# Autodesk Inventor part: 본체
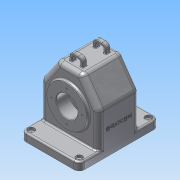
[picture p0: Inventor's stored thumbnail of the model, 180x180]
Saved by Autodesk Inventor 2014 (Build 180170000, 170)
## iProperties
Created: 2016-12
Part Number: 본체
Material: 알루미늄 6061
Document SubType Name: Modeling
Designer: net
Density: 2.71 g/cm^3
Appearance: 알루미늄 - 평지
Author: net
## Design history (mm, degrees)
sketch "스케치1"
  geometry: L1 (-55, 75)-(55, 75); L2 (55, 75)-(55, -75); L3 (55, -75)-(-55, -75); L4 (-55, -75)-(-55, 75); L5 (-55, 75)-(55, -75); L6 (55, 75)-(-55, -75); 1 further point
  constraints: 12 end point, 2 midpoint, 2 parallel, 1 horizontal, 1 perpendicular
  dimensions: "d0" = 110 distance between parallel lines of L4 L2; "d1" = 150 distance between parallel lines of L1 L3
extrude "돌출1" new body sketch "스케치1" distance "d2" = 15; taper "d3" = 0 deg
sketch "스케치2"
  geometry: L1 (-55, 80)-(-55, 15); L2 (-55, 15)-(55, 15); L3 (55, 15)-(55, 80); L4 (55, 80)-(23.491, 125); L5 (23.491, 125)-(-23.491, 125); L6 (-23.491, 125)-(-55, 80); L7 (55, 15)-(-55, 15) reference; L8 (-55, 0)-(-55, 15) reference; L9 (-55, 0)-(55, 0) reference; 3 further points
  constraints: 12 end point, 2 collinear, 2 midpoint, 2 parallel, 2 vertical alignment, 1 perpendicular, 1 vertical
  dimensions: "d4" = 35 deg angle of L1 L6; "d5" = 35 deg angle of L3 L4; "d6" = 125 distance between parallel lines of L9 L5; "d7" = 80 distance from line of L9 L3.end
extrude "돌출2" join sketch "스케치2" stored distance "d8" = 77; taper "d9" = 0 deg
sketch "스케치3"
  geometry: C1 r 37.5 at (0, 65); 1 further point
  constraints: 1 centre point, 1 vertical alignment
  dimensions: "d10" = 75 diameter of C1; "d11" = 65 distance of point (0, 0) C1.centre
extrude "돌출3" join sketch "스케치3" distance "d12" = 5; taper "d13" = 0 deg
sketch "스케치4"
  geometry: C1 r 37.5 at (0, 65) reference; C2 r 31 at (0, 65); 1 further point
  constraints: 1 centre point, 1 coincident
  dimensions: "d14" = 62 diameter of C2
extrude "돌출4" join sketch "스케치4" distance "d15" = 10; taper "d16" = 0 deg
sketch "스케치5"
  geometry: L1 (-55, 15)-(-55, 80) reference; L2 (-55, 80)-(-23.491, 125) reference; L3 (-23.491, 125)-(23.491, 125) reference; L4 (23.491, 125)-(55, 80) reference; L5 (55, 80)-(55, 15) reference; L6 (50, 0)-(50, 78.424); L7 (50, 78.424)-(20.888, 120); L8 (20.888, 120)-(-20.888, 120); L9 (-20.888, 120)-(-50, 78.424); L10 (-50, 78.424)-(-50, 0); L11 (-55, 0)-(55, 0) reference; L12 (-50, 0)-(50, 0); 1 further point
  constraints: 12 end point, 2 equal length, 2 point on line, 1 collinear, 2 other
  dimensions: "d17" = 5 distance between parallel lines of L5 L6; "d18" = 5 distance between parallel lines of L4 L7
extrude "돌출5" cut sketch "스케치5" stored distance "d19" = 67; taper "d20" = 0 deg
node "작업 평면1"
sketch "스케치13"
  geometry: C1 r 31 at (0, 0) reference; C2 r 27 at (0, 0); 1 further point
  constraints: 1 centre point, 1 coincident
  dimensions: "d132" = 54 diameter of C2
extrude "돌출10" join sketch "스케치13" stored distance "d133" = 15; taper "d134" = 45 deg
hole "구멍1" diameter "d23" = 40; stored, may be unused: countersink angle "d27" = 90 deg, drill point angle "d29" = 118 deg; dims "d21" = 10, "d22" = 10, "d24" = 6, "d25" = 4, "d26" = 2, "d28" = 8
sketch "스케치6"
  geometry: C1 r 20 at (0, 0) reference; 2 further points
  constraints: 1 vertical alignment
  dimensions: "d30" = 29 distance of C1.centre point (0, 29)
hole "구멍2" sketch "스케치6" at (0, 29) diameter "d31" = 2.459; stored, may be unused: countersink angle "d35" = 90 deg, drill point angle "d37" = 118 deg; dims "d32" = 6, "d33" = 4, "d34" = 2, "d36" = 8
sketch "스케치7"
  geometry: C1 r 20 at (0, 0) reference; 2 further points
  constraints: 1 vertical alignment
  dimensions: "d41" = 26 distance of C1.centre point (0, 26)
hole "구멍3" sketch "스케치7" at (0, 26) diameter "d42" = 2.459; stored, may be unused: countersink angle "d46" = 90 deg, drill point angle "d48" = 118 deg; dims "d43" = 6, "d44" = 4, "d45" = 2, "d47" = 8
fillet "모깎기1" dims "d52" = 10
sketch "스케치8"
  geometry: L1 (-55, 65)-(-55, 38.5) reference; L2 (-55, 38.5)-(55, 38.5) reference; L3 (55, 38.5)-(55, 65) reference; L4 (45, 75)-(-45, 75) reference; C1 r 6 at (-45, 65); C2 r 6 at (45, 65); C3 r 6 at (45, -65); C4 r 6 at (-45, -65); A1 r 10 centre (-45, -65) between (-55, -65) and (-45, -75) reference; A2 r 10 centre (45, -65) between (45, -75) and (55, -65) reference; A3 r 10 centre (-45, 65) between (-45, 75) and (-55, 65) reference; A4 r 10 centre (45, 65) between (55, 65) and (45, 75) reference; 1 further point
  constraints: 4 centre point, 4 coincident, 3 equal radius
  dimensions: "d53" = 12 diameter of C4
extrude "돌출6" cut sketch "스케치8" distance "d54" = 5; taper "d55" = 0 deg
hole "구멍4" diameter "d58" = 5; stored, may be unused: countersink angle "d62" = 90 deg, drill point angle "d64" = 118 deg; dims "d56" = 10, "d57" = 10, "d59" = 6, "d60" = 4, "d61" = 2, "d63" = 8
hole "구멍5" diameter "d67" = 5; stored, may be unused: countersink angle "d71" = 90 deg, drill point angle "d73" = 118 deg; dims "d65" = 10, "d66" = 10, "d68" = 6, "d69" = 4, "d70" = 2, "d72" = 8
hole "구멍6" diameter "d76" = 5; stored, may be unused: countersink angle "d80" = 90 deg, drill point angle "d82" = 118 deg; dims "d74" = 10, "d75" = 10, "d77" = 6, "d78" = 4, "d79" = 2, "d81" = 8
hole "구멍7" diameter "d85" = 5; stored, may be unused: countersink angle "d89" = 90 deg, drill point angle "d91" = 118 deg; dims "d83" = 10, "d84" = 10, "d86" = 6, "d87" = 4, "d88" = 2, "d90" = 8
sketch "스케치9"
  geometry: L1 (35.991, 20.5)-(10.991, 20.5); L2 (10.991, 20.5)-(10.991, 12.5); L3 (10.991, 12.5)-(35.991, 12.5); L4 (35.991, 12.5)-(35.991, 20.5); L5 (35.991, 20.5)-(10.991, 12.5); L6 (10.991, 20.5)-(35.991, 12.5); L7 (10.991, 56.5)-(35.991, 56.5); L8 (35.991, 56.5)-(35.991, 64.5); L9 (35.991, 64.5)-(10.991, 64.5); L10 (10.991, 64.5)-(10.991, 56.5); L11 (10.991, 56.5)-(35.991, 64.5); L12 (35.991, 56.5)-(10.991, 64.5); 5 further points
  constraints: 24 end point, 6 midpoint, 4 parallel, 2 horizontal, 2 perpendicular, 2 vertical alignment, 1 collinear
  dimensions: "d92" = 25 distance between parallel lines of L4 L2; "d94" = 36 distance between parallel lines of L7 L1; "d95" = 52 distance between parallel lines of L9 L3; "d97" = 8 distance between parallel lines of L1 L3; "d99" = 18 distance from line of point (23.491, 38.5) L1
extrude "돌출7" join sketch "스케치9" distance "d100" = 15; taper "d101" = 0 deg
sketch "스케치10"
  geometry: L1 (25, 0)-(0, 0) reference; L2 (0, 15)-(25, 15) reference; L3 (5, 10)-(20, 10); L4 (20, 10)-(20, 0); L5 (20, 0)-(5, 0); L6 (5, 0)-(5, 10); 3 further points
  constraints: 8 end point, 2 midpoint, 2 parallel, 1 collinear, 1 horizontal, 1 perpendicular, 1 vertical alignment
  dimensions: "d102" = 15 distance between parallel lines of L4 L6; "d103" = 5 distance between parallel lines of L2 L3
extrude "돌출8" cut sketch "스케치10" stored distance "d104" = 15; taper "d105" = 0 deg
fillet "모깎기2" dims "d106" = 8
fillet "모깎기3" dims "d107" = 3
fillet "모깎기4" dims "d108" = 1
fillet "모깎기9" dims "d117" = 10
fillet "모깎기10" dims "d118" = 8
fillet "모깎기11" dims "d119" = 3
fillet "모깎기12" dims "d120" = 3
fillet "모깎기13" dims "d121" = 3
fillet "모깎기14" dims "d122" = 3
fillet "모깎기15" dims "d123" = 1
fillet "모깎기16" dims "d124" = 1
fillet "모깎기17" dims "d125" = 10
chamfer "모따기1" distance "d126" = 1; stored, may be unused: second distance "d127" = 2, angle "d128" = 45 deg
chamfer "모따기2" distance "d129" = 1; stored, may be unused: second distance "d130" = 2, angle "d131" = 45 deg
fillet "모깎기18" dims "d135" = 3
sketch "스케치14"
  geometry: L1 (26.5, 76.847)-(26.5, 18) reference; L2 (140, 0)-(130, 0) reference; 2 further points
  constraints: 1 other
  dimensions: "d136" = 38 distance from line of L1 point (64.5, 45); "d137" = 45 distance from line of L2 point (64.5, 45)
feature "엠보싱1" sketch "스케치14" dims "d4" = 35 deg, "d5" = 35 deg, "d6" = 125, "d7" = 80, "d138" = 0.5, "d139" = 0
node "솔리드1"
pattern_circular "원형 패턴1" dims angle "d39" = 360 deg
pattern_circular "원형 패턴2" dims angle "d50" = 360 deg
node "투영된 루프1"
other parameters: "d111" = -24
